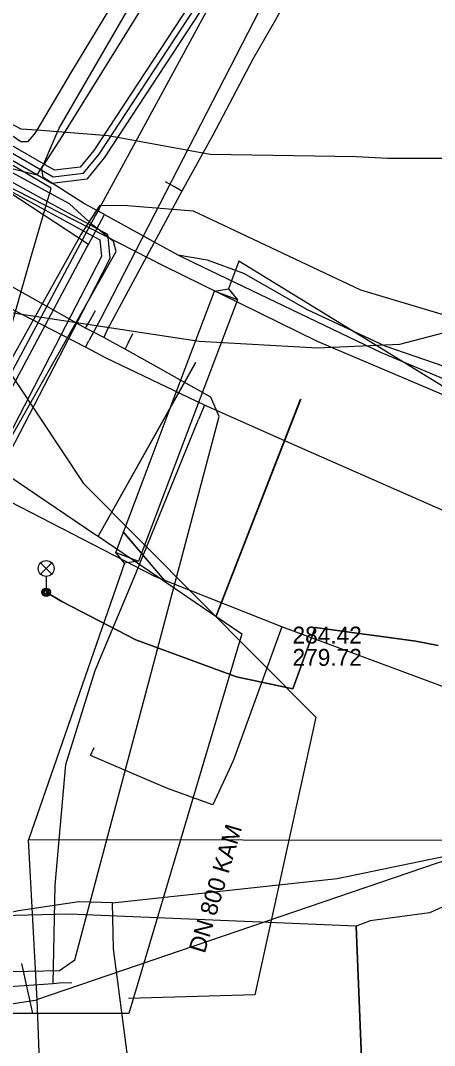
# Model space of a CAD drawing. Extents: x -599854 to -599675, y -1160809 to -1160543.
# Drawn here: x -599819.46 to -599799.9, y -1160620.79 to -1160572.33 of the extents above; entities that cross this region are included whole.
import ezdxf

# ---------------------------------------------------------------- set-up
doc = ezdxf.new("R2010")
doc.units = 0
for name, color, linetype in [('BKOM-ODVODNENI_trasa sítě', 7, 'Continuous'), ('BVK-JEDNOTNA_popisy', 7, 'Continuous'), ('BVK-JEDNOTNA_trasa sítě', 7, 'Continuous'), ('BVK-KANALIZACE_ vyřazená trasa sítě', 7, 'Continuous'), ('BVK-VODOVOD_trasa sítě', 7, 'Continuous'), ('BVK-VODOVOD_trasa zrušené sítě', 7, 'Continuous'), ('CETIN_kabel podzemní', 7, 'Continuous'), ('CETIN_kabel podzemní neprovozovaný', 7, 'Continuous'), ('DESTOVA_trasa neprovozované sítě', 7, 'Continuous'), ('DPMB_kabel', 7, 'Continuous'), ('DPMB_kyneta', 7, 'Continuous'), ('DPMB_trolejové vedení-nosné lano', 7, 'Continuous'), ('EON-NN_kabel', 7, 'Continuous'), ('EON-NN_kabel zrušené sítě', 7, 'Continuous'), ('INNOGY-STL_trasa sítě', 7, 'Continuous'), ('TSB_kabel VO', 7, 'Continuous'), ('TSB_lampy VO', 7, 'Continuous')]:
    doc.layers.add(name, color=color, linetype=linetype)

msp = doc.modelspace()

# ---------------------------------------------------------------- linework, layer by layer
at = {"layer": 'BKOM-ODVODNENI_trasa sítě'}
for points in [[(-599811.189, -1160588.493), (-599815.795, -1160596.712)], [(-599806.221, -1160590.235), (-599810.22, -1160600.49)], [(-599814.624, -1160596.507), (-599812.592, -1160598.884)]]:
    msp.add_lwpolyline(points, dxfattribs=at)
at = {"layer": 'BVK-JEDNOTNA_popisy'}
msp.add_line((-599806.607, -1160601.911), (-599806.607, -1160601.911), dxfattribs=at)
at = {"layer": 'BVK-JEDNOTNA_trasa sítě'}
msp.add_line((-599809, -1160601.32), (-599814.34, -1160619.27), dxfattribs=at)
for points in [[(-599844.85, -1160577.01), (-599835.874, -1160583.097), (-599835.609, -1160583.276), (-599829.7, -1160587.283), (-599829.617, -1160587.34), (-599815.952, -1160596.606), (-599815.795, -1160596.712), (-599812.592, -1160598.884), (-599812.551, -1160598.912), (-599810.515, -1160600.293), (-599810.225, -1160600.489), (-599809, -1160601.32)], [(-599814.34, -1160619.27), (-599818.89, -1160619.268), (-599819.88, -1160619.268), (-599825.3, -1160619.266), (-599832.61, -1160619.263), (-599837.36, -1160619.261), (-599838.683, -1160619.26), (-599839.75, -1160619.26)]]:
    msp.add_lwpolyline(points, dxfattribs=at)
at = {"layer": 'BVK-KANALIZACE_ vyřazená trasa sítě'}
for p, q in [((-599816.486, -1160594.211), (-599805.5, -1160605.27)), ((-599805.5, -1160605.27), (-599808.39, -1160618.39)), ((-599808.39, -1160618.39), (-599814.36, -1160618.556))]:
    msp.add_line(p, q, dxfattribs=at)
for points in [[(-599822.796, -1160585.73), (-599821.384, -1160585.908), (-599811.025, -1160587.485), (-599805.422, -1160587.8), (-599801.54, -1160587.634), (-599791.243, -1160584.941), (-599789.279, -1160584.062), (-599787.442, -1160583.059), (-599785.884, -1160582.21), (-599784.335, -1160581.226), (-599782.303, -1160579.92), (-599781.529, -1160579.068)], [(-599822.796, -1160585.73), (-599822.412, -1160586.686), (-599820.726, -1160587.859), (-599816.486, -1160594.211)]]:
    msp.add_lwpolyline(points, dxfattribs=at)
at = {"layer": 'BVK-VODOVOD_trasa sítě'}
for p, q in [((-599815.53, -1160587.31), (-599815.98, -1160587.08)), ((-599815.36, -1160586.95), (-599815.53, -1160587.31)), ((-599815.093, -1160587.551), (-599815.53, -1160587.31)), ((-599814.93, -1160587.64), (-599815.093, -1160587.551))]:
    msp.add_line(p, q, dxfattribs=at)
for points in [[(-599773.52, -1160553.4), (-599779.95, -1160553.74), (-599785.89, -1160554.08), (-599789.37, -1160554.47), (-599792.01, -1160555.84), (-599793.4, -1160556.58), (-599795.21, -1160557.59), (-599797.11, -1160559.34), (-599801.61, -1160563.26), (-599803.76, -1160565.39), (-599806.64, -1160570.9), (-599807.42, -1160572.3), (-599808.48, -1160574.16), (-599810.38, -1160577.75), (-599811.83, -1160580.4), (-599815.36, -1160586.95)], [(-599815.98, -1160587.08), (-599816.39, -1160586.87), (-599822, -1160583.72), (-599827.25, -1160580.9), (-599830.01, -1160579.46), (-599835.52, -1160576.6), (-599838.52, -1160575.08), (-599843.3, -1160570.99)], [(-599811.83, -1160580.4), (-599812.191, -1160580.193), (-599812.607, -1160579.958)], [(-599816.39, -1160586.87), (-599816.23, -1160586.61), (-599815.92, -1160586.04)], [(-599814.51, -1160587.87), (-599814.38, -1160587.59), (-599814.153, -1160587.127)], [(-599846.27, -1160618.35), (-599845.87, -1160618.34), (-599845.21, -1160617.96), (-599843.85, -1160617.9), (-599840.06, -1160617.72), (-599837.75, -1160617.67), (-599817.61, -1160617.24), (-599816.89, -1160616.73), (-599813.48, -1160603.89), (-599810.07, -1160591.05), (-599810.46, -1160590.14), (-599814.51, -1160587.87), (-599814.93, -1160587.64)]]:
    msp.add_lwpolyline(points, dxfattribs=at)
at = {"layer": 'BVK-VODOVOD_trasa zrušené sítě'}
for p, q in [((-599816.383, -1160587.777), (-599827.89, -1160581.85)), ((-599816.383, -1160587.777), (-599816.228, -1160587.481)), ((-599810.766, -1160590.517), (-599811.05, -1160591.2)), ((-599806.4, -1160592.46), (-599810.766, -1160590.517)), ((-599817.626, -1160617.828), (-599817.031, -1160617.799)), ((-599817.921, -1160617.85), (-599817.626, -1160617.828))]:
    msp.add_line(p, q, dxfattribs=at)
for points in [[(-599723.312, -1160596.189), (-599723.552, -1160595.075), (-599725.385, -1160585.124), (-599727.088, -1160577.648), (-599730.061, -1160573.561), (-599730.185, -1160573.396), (-599730.663, -1160572.731), (-599734.747, -1160567.144), (-599747.147, -1160556.314), (-599750.794, -1160554.698), (-599754.863, -1160552.892), (-599773.118, -1160554.584), (-599787.156, -1160555.886), (-599789.075, -1160557.142), (-599798.149, -1160563.04), (-599806.144, -1160568.237), (-599808.168, -1160571.846), (-599815.66, -1160586.425), (-599816.228, -1160587.481)], [(-599810.766, -1160590.517), (-599815.41, -1160588.3), (-599816.383, -1160587.777)], [(-599817.921, -1160617.85), (-599817.82, -1160613.21), (-599817.32, -1160607.5), (-599815.93, -1160603.06), (-599814.017, -1160598.476), (-599811.05, -1160591.2)], [(-599769.626, -1160601.428), (-599783.571, -1160602.504), (-599806.4, -1160592.46)], [(-599846.98, -1160618.37), (-599843.851, -1160618.458), (-599820.2, -1160618.014), (-599817.921, -1160617.85)]]:
    msp.add_lwpolyline(points, dxfattribs=at)
at = {"layer": 'CETIN_kabel podzemní'}
for points in [[(-599760.54, -1160548.25), (-599763.79, -1160549.79), (-599775.39, -1160551.91), (-599776.73, -1160551.13), (-599777.24, -1160548.01), (-599779.6, -1160547.75), (-599787.47, -1160549.87), (-599795.94, -1160553.78), (-599800.44, -1160556.65), (-599809.68, -1160565.19), (-599817.48, -1160577.77), (-599818.39, -1160579.19)], [(-599814.4, -1160581.07), (-599811.3, -1160581.33), (-599803.39, -1160585.07), (-599799.44, -1160586.24), (-599796.45, -1160587.12), (-599794.41, -1160586.52), (-599780.55, -1160576.54), (-599778.97, -1160574.64), (-599776.87, -1160571.64), (-599775.34, -1160571.18), (-599766.27, -1160570.81), (-599760.94, -1160571.57), (-599759.27, -1160573.58), (-599754.54, -1160576.32), (-599750.34, -1160581.07), (-599747.4, -1160585.47), (-599742.37, -1160594.32)], [(-599823.44, -1160578.45), (-599818.67, -1160579.62), (-599818.39, -1160579.19)], [(-599823.04, -1160593.97), (-599816.62, -1160582.5), (-599815.69, -1160581.06), (-599814.4, -1160581.07)], [(-599815.12, -1160614.04), (-599816.71, -1160614), (-599819.55, -1160614.42), (-599820.67, -1160614.66), (-599821.43, -1160614.69)], [(-599813.64, -1160626.29), (-599814.01, -1160624.26), (-599815.06, -1160616.21), (-599815.12, -1160614.04)]]:
    msp.add_lwpolyline(points, dxfattribs=at)
at = {"layer": 'CETIN_kabel podzemní neprovozovaný'}
for points in [[(-599818.09, -1160578.47), (-599817.64, -1160577.42), (-599814.15, -1160571.42)], [(-599816.25, -1160582.92), (-599821.13, -1160579.72), (-599823.44, -1160578.45)], [(-599818.39, -1160579.19), (-599818.09, -1160578.47)], [(-599815.49, -1160581.5), (-599816.43, -1160580.99), (-599818.39, -1160579.76), (-599818.45, -1160579.33), (-599818.39, -1160579.19)], [(-599816.25, -1160582.92), (-599815.49, -1160581.5)], [(-599815.49, -1160581.5), (-599813.032, -1160582.853)], [(-599821.91, -1160594.08), (-599821.99, -1160593.67), (-599816.34, -1160583.08), (-599816.25, -1160582.92)], [(-599813.032, -1160582.853), (-599812.02, -1160583.41)], [(-599812.02, -1160583.41), (-599810.64, -1160583.64), (-599808.92, -1160584.27), (-599805.91, -1160586), (-599802.25, -1160587.71), (-599797.54, -1160589.34), (-599791.15, -1160591.37), (-599790.79, -1160591.51)], [(-599812.02, -1160583.41), (-599811.253, -1160583.779)], [(-599811.253, -1160583.779), (-599802.42, -1160588.03), (-599797.67, -1160590.02), (-599791.5, -1160592.22), (-599791.17, -1160592.27)], [(-599807.11, -1160601), (-599813.11, -1160598.61), (-599821.91, -1160594.08)], [(-599807.11, -1160601), (-599809.41, -1160607.33)], [(-599796.74, -1160604.91), (-599799.22, -1160603.92), (-599807.11, -1160601)], [(-599809.41, -1160607.33), (-599810.37, -1160609.41), (-599812.51, -1160608.64), (-599816.15, -1160607.07), (-599815.98, -1160606.69)], [(-599815.12, -1160614.04), (-599804.5, -1160612.89), (-599799.33, -1160611.82), (-599796.91, -1160609.47), (-599794.64, -1160607.36)]]:
    msp.add_lwpolyline(points, dxfattribs=at)
at = {"layer": 'DESTOVA_trasa neprovozované sítě'}
for p, q in [((-599811.19, -1160588.52), (-599815.795, -1160596.712)), ((-599806.24, -1160590.25), (-599810.225, -1160600.489)), ((-599814.61, -1160596.5), (-599812.592, -1160598.884)), ((-599819.419, -1160616.904), (-599818.89, -1160619.268))]:
    msp.add_line(p, q, dxfattribs=at)
at = {"layer": 'DPMB_kabel'}
for points in [[(-599854.3744, -1160570.8811), (-599853.98, -1160571.11), (-599853.34, -1160571.94), (-599850.41, -1160575.09), (-599849.54, -1160575.55), (-599841.94, -1160567.75), (-599841.46, -1160567.86), (-599836.83, -1160571.43), (-599830.31, -1160574.99), (-599826.68, -1160574.81), (-599821.59, -1160577.6), (-599817.92, -1160579.72), (-599816.48, -1160579.55), (-599815.751, -1160578.652), (-599810.91, -1160571.26), (-599805.31, -1160565.16), (-599798.95, -1160559.8), (-599795.69, -1160558.33), (-599784.88, -1160555), (-599775.62, -1160554.42), (-599765.57, -1160554.12), (-599753.796, -1160555.833), (-599746.11, -1160559.64), (-599743.15, -1160562.7)], [(-599854.3744, -1160570.8811), (-599853.98, -1160571.11), (-599853.34, -1160571.94), (-599850.41, -1160575.09), (-599849.54, -1160575.55), (-599841.94, -1160567.75), (-599841.46, -1160567.86), (-599836.83, -1160571.43), (-599830.31, -1160574.99), (-599826.68, -1160574.81), (-599821.59, -1160577.6), (-599817.92, -1160579.72), (-599816.48, -1160579.55), (-599815.751, -1160578.652), (-599810.91, -1160571.26), (-599805.31, -1160565.16), (-599798.95, -1160559.8), (-599795.69, -1160558.33), (-599784.88, -1160555), (-599775.62, -1160554.42), (-599765.57, -1160554.12), (-599753.796, -1160555.833), (-599746.11, -1160559.64), (-599743.15, -1160562.7)], [(-599799.111, -1160559.544), (-599805.518, -1160564.943), (-599811.148, -1160571.075), (-599815.994, -1160578.475), (-599816.636, -1160579.266), (-599817.856, -1160579.41), (-599821.443, -1160577.339), (-599826.61, -1160574.506), (-599830.24, -1160574.686), (-599836.666, -1160571.178), (-599841.329, -1160567.582), (-599842.037, -1160567.42), (-599849.598, -1160575.18), (-599850.225, -1160574.849), (-599853.111, -1160571.746), (-599853.778, -1160570.88), (-599854.3744, -1160570.5339)], [(-599799.111, -1160559.544), (-599805.518, -1160564.943), (-599811.148, -1160571.075), (-599815.994, -1160578.475), (-599816.636, -1160579.266), (-599817.856, -1160579.41), (-599821.443, -1160577.339), (-599826.61, -1160574.506), (-599830.24, -1160574.686), (-599836.666, -1160571.178), (-599841.329, -1160567.582), (-599842.037, -1160567.42), (-599849.598, -1160575.18), (-599850.225, -1160574.849), (-599853.111, -1160571.746), (-599853.778, -1160570.88), (-599854.3744, -1160570.5339)]]:
    msp.add_lwpolyline(points, dxfattribs=at)
at = {"layer": 'DPMB_kyneta'}
msp.add_lwpolyline([(-599775.601, -1160554.719), (-599784.826, -1160555.297), (-599795.584, -1160558.611), (-599798.789, -1160560.056), (-599805.102, -1160565.377), (-599810.672, -1160571.445), (-599815.508, -1160578.829), (-599816.324, -1160579.834), (-599817.984, -1160580.03), (-599821.737, -1160577.861), (-599826.75, -1160575.114), (-599830.38, -1160575.294), (-599836.994, -1160571.682), (-599841.591, -1160568.138), (-599841.843, -1160568.08), (-599849.482, -1160575.92), (-599850.595, -1160575.331), (-599853.569, -1160572.134), (-599854.182, -1160571.34), (-599854.3744, -1160571.2283)], dxfattribs=at)
at = {"layer": 'DPMB_trolejové vedení-nosné lano'}
for points in [[(-599809.14, -1160583.7), (-599809.637, -1160585.016)], [(-599791.2, -1160594.72), (-599809.14, -1160583.7)], [(-599812.2, -1160590.15), (-599810.295, -1160585.122)], [(-599809.214, -1160585.531), (-599810.295, -1160585.122), (-599809.637, -1160585.016), (-599809.214, -1160585.531)], [(-599809.214, -1160585.531), (-599811.14, -1160590.64)], [(-599813.48, -1160593.55), (-599812.2, -1160590.15)], [(-599811.14, -1160590.64), (-599812.44, -1160594.06)], [(-599814.963, -1160597.475), (-599813.48, -1160593.55)], [(-599812.44, -1160594.06), (-599813.882, -1160597.884)], [(-599813.882, -1160597.884), (-599814.54, -1160597.99), (-599814.963, -1160597.475), (-599813.882, -1160597.884)], [(-599814.54, -1160597.99), (-599819.08, -1160611.06)], [(-599818.68, -1160618.62), (-599819.08, -1160611.06)], [(-599798.82, -1160611.1), (-599819.08, -1160611.06)], [(-599818.683, -1160618.617), (-599797.73, -1160611.46)], [(-599819.99, -1160618.83), (-599818.68, -1160618.62)], [(-599818.68, -1160618.62), (-599818.683, -1160618.617)], [(-599818.64, -1160619.44), (-599818.68, -1160618.62)], [(-599818.53, -1160622.33), (-599818.64, -1160619.44)]]:
    msp.add_lwpolyline(points, dxfattribs=at)
at = {"layer": 'EON-NN_kabel'}
for points in [[(-599796.78, -1160553.49), (-599801.45, -1160556.33), (-599804.8, -1160558.95), (-599806.9, -1160560.72), (-599808.2, -1160561.99), (-599809.4, -1160563.31), (-599811.2, -1160565.43), (-599811.8, -1160566.46), (-599812.69, -1160567.72), (-599814.26, -1160570.12), (-599817.09, -1160574.82), (-599818.695, -1160577.517), (-599818.81, -1160577.71), (-599819.13, -1160578.07), (-599819.44, -1160578.07), (-599820.432, -1160577.383), (-599821.126, -1160576.901), (-599821.2, -1160576.85), (-599821.285, -1160576.478), (-599821.33, -1160576.28), (-599821.329, -1160576.276), (-599821.173, -1160575.723), (-599821.15, -1160575.64)], [(-599821.961, -1160621.523), (-599822.2, -1160617.195), (-599822.31, -1160614.464), (-599821.801, -1160611.233), (-599822.441, -1160608.569), (-599823.091, -1160600.812), (-599822.879, -1160596.291), (-599822.768, -1160596.219), (-599822.254, -1160595.755), (-599821.35, -1160594.94), (-599820.74, -1160593.48), (-599816.268, -1160585.593), (-599814.94, -1160583.25), (-599815.06, -1160582.78), (-599815.324, -1160582.571), (-599815.78, -1160582.21), (-599816.02, -1160582.02), (-599817.151, -1160581.004), (-599818.08, -1160580.497), (-599821.764, -1160578.485), (-599821.689, -1160577.998), (-599821.126, -1160576.901), (-599820.987, -1160576.629), (-599820.65, -1160575.973)]]:
    msp.add_lwpolyline(points, dxfattribs=at)
at = {"layer": 'EON-NN_kabel zrušené sítě'}
for points in [[(-599796.77, -1160578.86), (-599802.11, -1160578.86), (-599803.6, -1160578.78), (-599810.5, -1160578.66), (-599815.32, -1160577.78), (-599818.695, -1160577.517), (-599819.43, -1160577.46), (-599820.256, -1160577.019), (-599820.987, -1160576.629), (-599821.06, -1160576.59), (-599821.233, -1160576.388), (-599821.329, -1160576.276), (-599821.443, -1160576.144), (-599821.48, -1160576.1), (-599821.25, -1160575.66)], [(-599821.142, -1160575.674), (-599821.173, -1160575.723), (-599821.443, -1160576.144), (-599822.456, -1160577.727), (-599822.64, -1160578.918), (-599818.31, -1160581.283), (-599815.712, -1160582.703), (-599815.628, -1160583.49), (-599821.004, -1160593.85), (-599822.044, -1160595.279), (-599823.223, -1160595.509)], [(-599823.127, -1160595.977), (-599822.254, -1160595.755), (-599821.815, -1160595.644), (-599820.662, -1160594.059), (-599816.268, -1160585.593), (-599815.218, -1160583.569), (-599815.324, -1160582.571), (-599815.337, -1160582.452), (-599815.78, -1160582.21), (-599818.195, -1160580.891), (-599822.202, -1160578.702), (-599822.073, -1160577.863), (-599821.285, -1160576.478), (-599821.233, -1160576.388), (-599820.908, -1160575.816)], [(-599832.197, -1160590.797), (-599831.898, -1160590.277), (-599831.63, -1160589.811), (-599827.017, -1160592.619), (-599824.425, -1160594.075), (-599822.331, -1160595.251), (-599818.989, -1160583.601), (-599818.31, -1160581.283), (-599818.195, -1160580.891), (-599818.08, -1160580.497), (-599818.01, -1160580.257), (-599820.977, -1160578.512), (-599820.432, -1160577.383), (-599820.256, -1160577.019), (-599819.985, -1160576.457)]]:
    msp.add_lwpolyline(points, dxfattribs=at)
at = {"layer": 'INNOGY-STL_trasa sítě'}
for points in [[(-599780.99, -1160552.44), (-599791.78, -1160554.03), (-599792.31, -1160554.45), (-599794.05, -1160555.73), (-599804.4, -1160563.49), (-599804.53, -1160563.48), (-599804.66, -1160563.47), (-599805.49, -1160563.4), (-599806.68, -1160563.29), (-599806.84, -1160563.28), (-599811.27, -1160567.47), (-599811.2, -1160567.91), (-599811.17, -1160568.07), (-599811.12, -1160568.36), (-599810.84, -1160570.05), (-599810.7, -1160570.94), (-599810.69, -1160571.01), (-599810.61, -1160571.46), (-599810.57, -1160571.72), (-599813.95, -1160577.93), (-599814.51, -1160578.96)], [(-599814.51, -1160578.96), (-599815.36, -1160580.52), (-599815.66, -1160581.07), (-599815.75, -1160581.24), (-599815.91, -1160581.54), (-599822.3, -1160593.45), (-599822.39, -1160593.61)]]:
    msp.add_lwpolyline(points, dxfattribs=at)
at = {"layer": 'TSB_kabel VO'}
for points in [[(-599854.3744, -1160555.1902), (-599854.04, -1160555.5), (-599849.6, -1160560.93), (-599846.5, -1160564.23), (-599842.34, -1160567.41), (-599836.14, -1160572.72), (-599835.53, -1160572.87), (-599830.9, -1160574.94), (-599826.66, -1160576.79), (-599812.72, -1160583.91), (-599805.44, -1160587.49), (-599799.47, -1160590.02), (-599798.76, -1160590.06), (-599794.55, -1160590.16), (-599791.05, -1160588.25), (-599791.37, -1160587.42), (-599790.5, -1160586.88), (-599785.83, -1160583.3), (-599779.31, -1160578.94), (-599776.23, -1160575.89), (-599774.72, -1160572.96), (-599774.64, -1160569.54), (-599766.89, -1160569.33), (-599766.71, -1160568.47)], [(-599799.72, -1160601.87), (-599800.78, -1160601.67), (-599805.54, -1160601.03), (-599806.6, -1160603.92), (-599809.25, -1160603.35), (-599814.01, -1160601.61), (-599817.5, -1160599.79), (-599818.25, -1160599.36), (-599817.5, -1160599.79), (-599814.01, -1160601.61), (-599809.25, -1160603.35), (-599806.6, -1160603.92), (-599805.54, -1160601.03), (-599800.78, -1160601.67), (-599799.72, -1160601.87)], [(-599797.31, -1160613.27), (-599800.14, -1160614.52), (-599802.94, -1160614.89), (-599803.6, -1160615.14), (-599803.35, -1160621.4)], [(-599800.51, -1160631.88), (-599801.66, -1160628.63), (-599803.35, -1160621.4), (-599803.6, -1160615.14), (-599817.16, -1160614.58), (-599825.47, -1160614.78), (-599827.84, -1160614.21), (-599835.21, -1160614.5), (-599849.27, -1160614.99), (-599854.3744, -1160615.0219)]]:
    msp.add_lwpolyline(points, dxfattribs=at)
at = {"layer": 'TSB_lampy VO'}
for p, q in [((-599818.515, -1160598.5), (-599817.985, -1160597.97)), ((-599818.515, -1160597.97), (-599817.985, -1160598.5)), ((-599818.515, -1160598.5), (-599817.985, -1160597.97)), ((-599818.515, -1160597.97), (-599817.985, -1160598.5)), ((-599818.25, -1160598.61), (-599818.25, -1160599.36)), ((-599818.25, -1160598.61), (-599818.25, -1160599.36))]:
    msp.add_line(p, q, dxfattribs=at)
for centre, radius in [((-599818.25, -1160598.235), 0.375), ((-599818.25, -1160598.235), 0.375), ((-599818.25, -1160599.36), 0.2), ((-599818.25, -1160599.36), 0.2), ((-599818.25, -1160599.36), 0.1445), ((-599818.25, -1160599.36), 0.1445), ((-599818.25, -1160599.36), 0.0876), ((-599818.25, -1160599.36), 0.0876)]:
    msp.add_circle(centre, radius, dxfattribs=at)

# ---------------------------------------------------------------- texts
at = {"layer": 'BVK-JEDNOTNA_popisy'}
for s, p in [('284.42', (-599806.607, -1160601.786)), ('279.72', (-599806.607, -1160602.836))]:
    msp.add_text(s, height=0.8, dxfattribs=at).set_placement(p)
msp.add_text('DN 800 KAM', height=0.8, rotation=73.43262, dxfattribs=at).set_placement((-599810.758, -1160616.467))

doc.saveas('drawing.dxf')
